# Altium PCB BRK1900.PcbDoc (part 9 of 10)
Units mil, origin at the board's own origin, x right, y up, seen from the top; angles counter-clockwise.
Board outline 8858.27 x 5905.51 mil, 10 copper layers (L1-TOP, L2-GND, L3-SIG1, L4-GND, L5-PWR, L6-PWR, L7-GND, L8-SIG2, L9-GND, L10-BOT), stack 48.824 mil thick; 507 components, 607 nets, 2498 pads, 2210 vias.
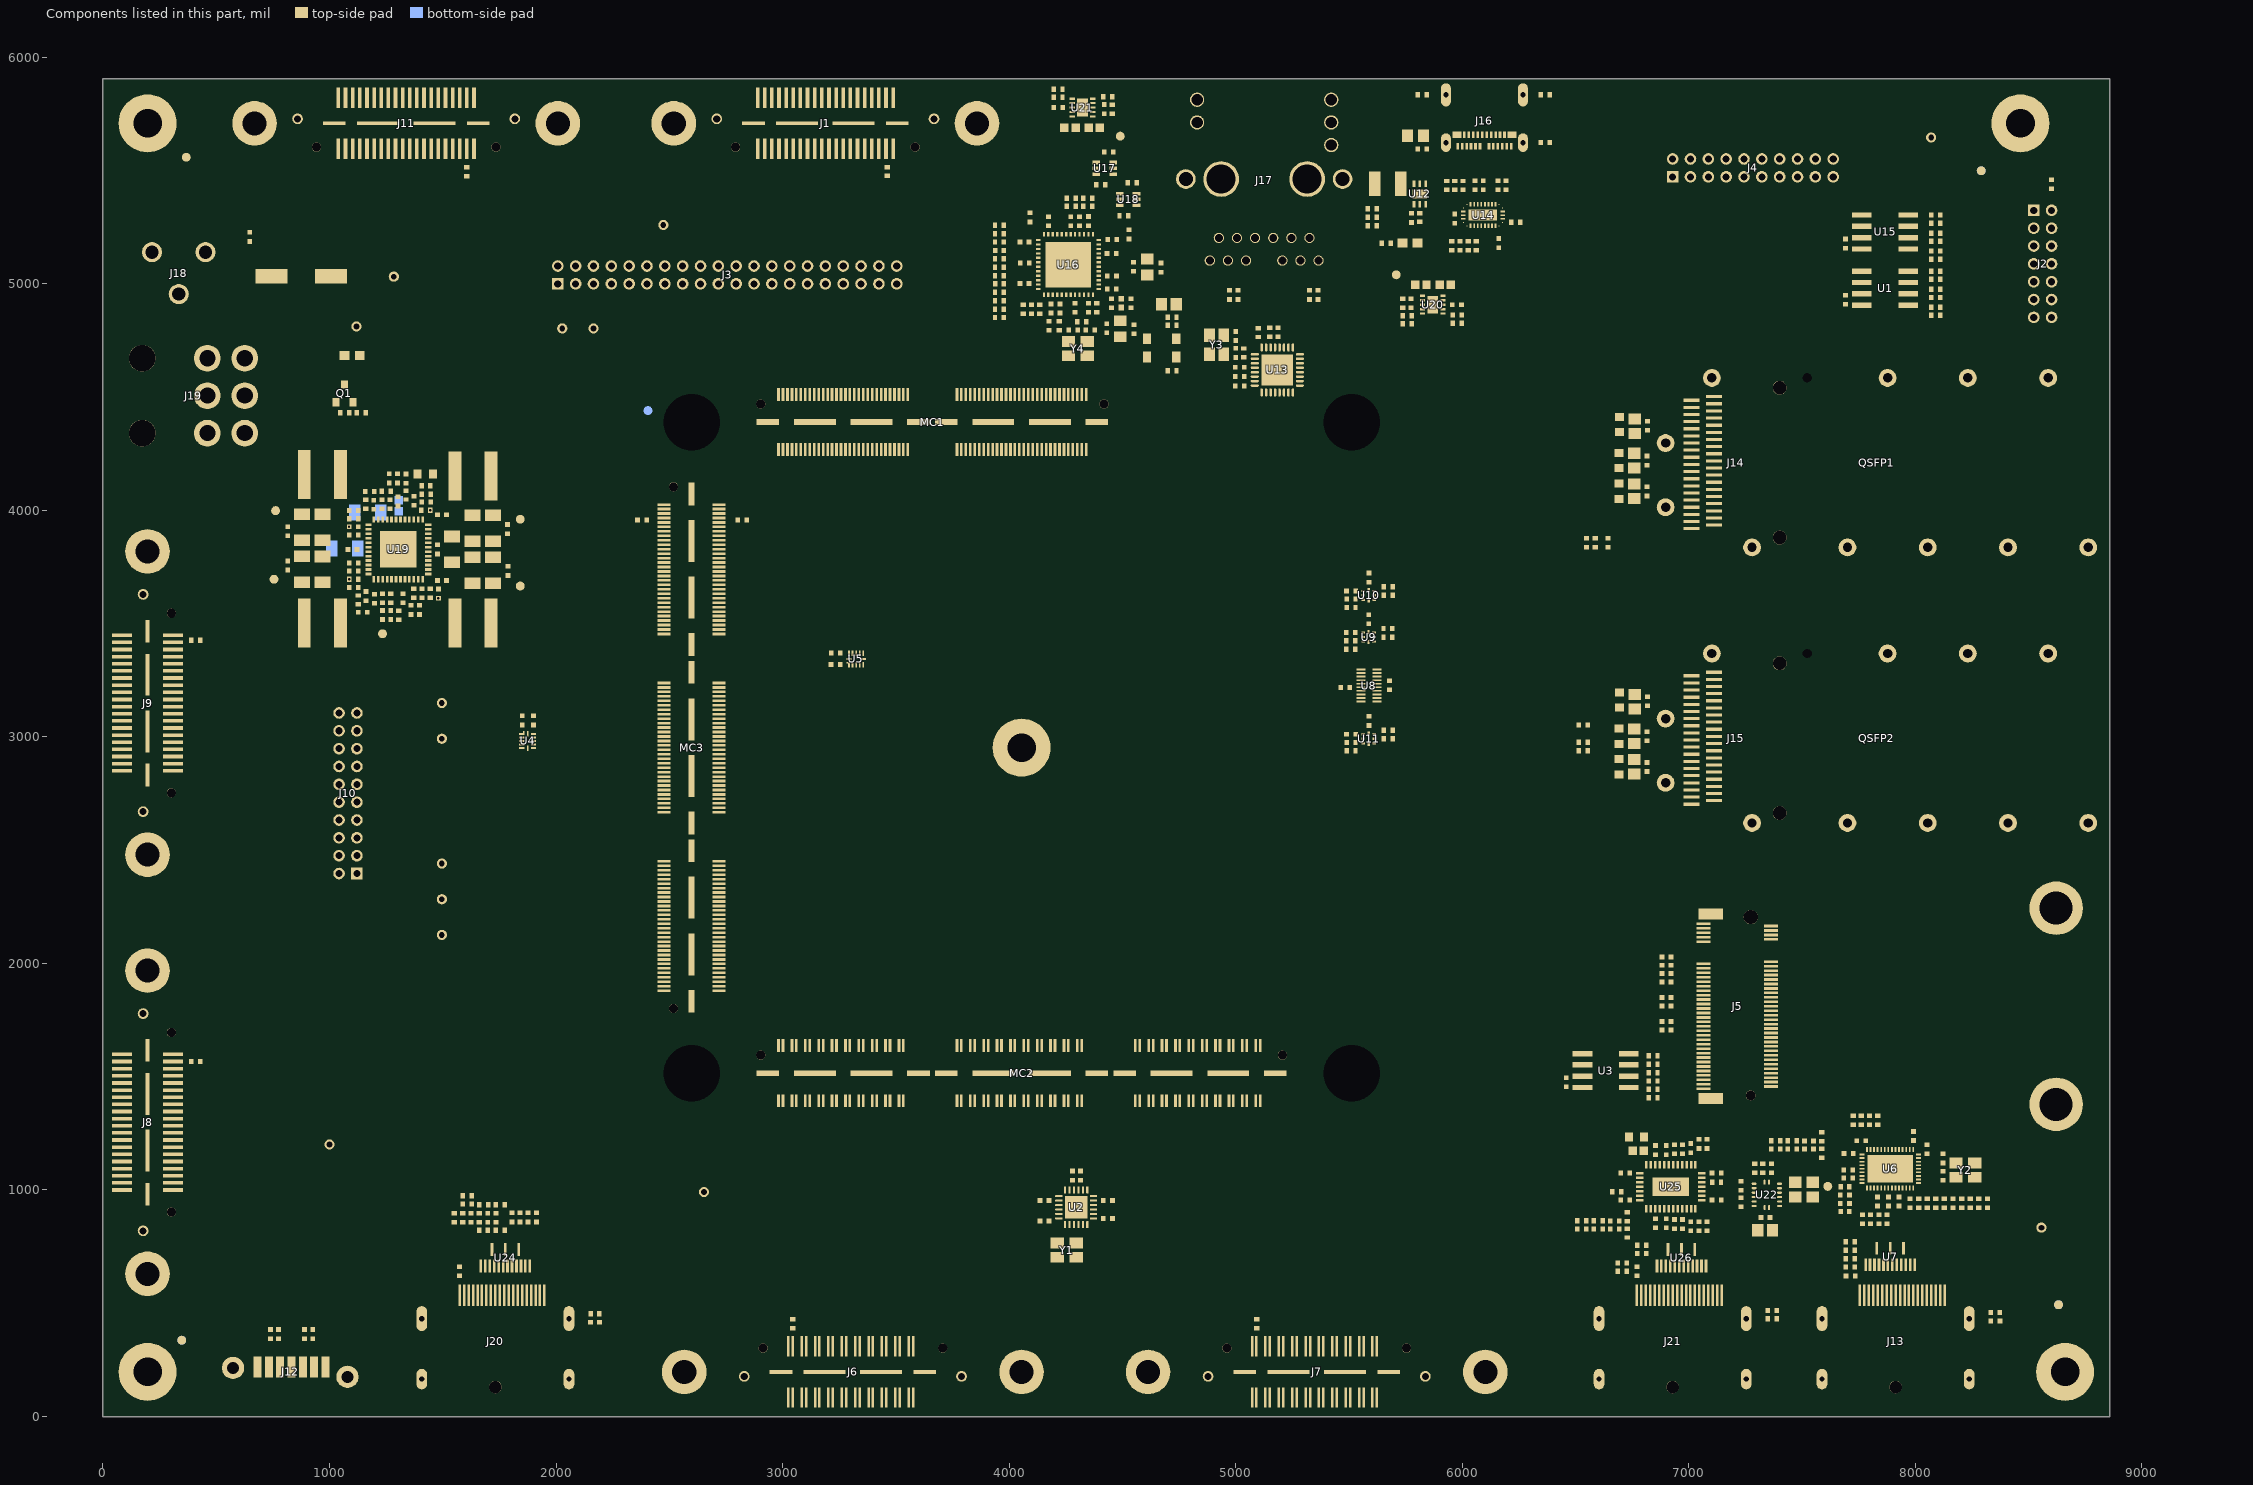
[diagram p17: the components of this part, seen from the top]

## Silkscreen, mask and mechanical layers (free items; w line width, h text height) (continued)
Fab Notes:
  drawing of 90 lines, arcs and shapes, not listed
  text "LAYER STACKUP TABLE" at 6751.97,9126.93 h50
  text "S" at 11192.76,9012.43 h90.87
  text "i" at 11229.19,9012.43 h90.87
  text "n" at 11250,9012.43 h90.87
  text "g" at 11291.64,9012.43 h90.87
  text "l" at 11328.07,9012.43 h90.87
  text "e" at 11348.89,9012.43 h90.87
  text "-" at 11390.52,9012.42 h90.87
  text "E" at 11416.54,9012.43 h90.87
  text "n" at 11452.97,9012.43 h90.87
  text "d" at 11494.61,9012.43 h90.87
  text "e" at 11536.24,9012.43 h90.87
  text "d" at 11577.88,9012.43 h90.87
  text "D" at 12207.26,9012.43 h90.87
  text "i" at 12254.1,9012.43 h90.87
  text "f" at 12274.91,9012.43 h90.87
  text "f" at 12300.94,9012.43 h90.87
  text "e" at 12326.96,9012.43 h90.87
  text "r" at 12368.59,9012.43 h90.87
  text "e" at 12394.61,9012.43 h90.87
  text "n" at 12436.25,9012.43 h90.87
  text "t" at 12477.88,9012.43 h90.87
  text "i" at 12503.91,9012.43 h90.87
  text "a" at 12524.72,9012.43 h90.87
  text "l" at 12561.15,9012.43 h90.87
  text "D" at 12639.07,9012.43 h90.87
  text "i" at 12685.91,9012.43 h90.87
  text "f" at 12706.73,9012.43 h90.87
  text "f" at 12732.75,9012.43 h90.87
  text "e" at 12758.77,9012.43 h90.87
  text "r" at 12800.41,9012.43 h90.87
  text "e" at 12826.43,9012.43 h90.87
  text "n" at 12868.06,9012.43 h90.87
  text "t" at 12909.7,9012.43 h90.87
  text "i" at 12935.72,9012.43 h90.87
  text "a" at 12956.54,9012.43 h90.87
  text "l" at 12992.97,9012.43 h90.87
  text "D" at 13122.91,9012.43 h90.87
  text "i" at 13169.75,9012.43 h90.87
  text "f" at 13190.57,9012.43 h90.87
  text "f" at 13216.59,9012.43 h90.87
  text "e" at 13242.61,9012.43 h90.87
  text "r" at 13284.25,9012.43 h90.87
  text "e" at 13310.27,9012.43 h90.87
  text "n" at 13351.9,9012.43 h90.87
  text "t" at 13393.54,9012.43 h90.87
  text "i" at 13419.56,9012.43 h90.87
  text "a" at 13440.38,9012.43 h90.87
  text "l" at 13476.81,9012.43 h90.87
  text "D" at 13554.72,9012.43 h90.87
  text "i" at 13601.56,9012.43 h90.87
  text "f" at 13622.38,9012.43 h90.87
  text "f" at 13648.4,9012.43 h90.87
  text "e" at 13674.42,9012.43 h90.87
  text "r" at 13716.06,9012.43 h90.87
  text "e" at 13742.08,9012.43 h90.87
  text "n" at 13783.72,9012.43 h90.87
  text "t" at 13825.35,9012.43 h90.87
  text "i" at 13851.37,9012.43 h90.87
  text "a" at 13872.19,9012.43 h90.87
  text "l" at 13908.62,9012.43 h90.87
  text "M" at 9938.93,9005.69 h85.82
  text "a" at 9996.18,9005.69 h85.82
  text "t" at 10037.82,9005.69 h85.82
  text "e" at 10058.64,9005.69 h85.82
  text "r" at 10100.27,9005.69 h85.82
  text "i" at 10126.29,9005.69 h85.82
  text "a" at 10141.91,9005.69 h85.82
  text "l" at 10183.54,9005.69 h85.82
  text "C" at 10339.53,8908.34 h90.87
  text "o" at 10381.17,8908.34 h90.87
  text "p" at 10422.8,8908.34 h90.87
  text "p" at 10464.44,8908.34 h90.87
  text "e" at 10506.07,8908.34 h90.87
  text "r" at 10547.71,8908.34 h90.87
  text "T" at 11322.82,8908.34 h90.87
  text "r" at 11359.25,8908.34 h90.87
  text "a" at 11385.27,8908.34 h90.87
  text "c" at 11421.7,8908.34 h90.87
  text "e" at 11452.93,8908.34 h90.87
  text "S" at 11681.8,8908.34 h90.87
  text "i" at 11718.23,8908.34 h90.87
  text "n" at 11739.05,8908.34 h90.87
  text "g" at 11780.68,8908.34 h90.87
  text "l" at 11817.11,8908.34 h90.87
  text "e" at 11837.93,8908.34 h90.87
  text "-" at 11879.56,8908.33 h90.87
  text "E" at 11905.59,8908.34 h90.87
  text "n" at 11942.02,8908.34 h90.87
  text "d" at 11983.65,8908.34 h90.87
  text "e" at 12025.29,8908.34 h90.87
  text "d" at 12066.92,8908.34 h90.87
  text "T" at 12311.31,8908.34 h90.87
  text "r" at 12347.74,8908.34 h90.87
  text "a" at 12373.76,8908.34 h90.87
  text "c" at 12410.19,8908.34 h90.87
  text "e" at 12441.42,8908.34 h90.87
  text "T" at 12743.12,8908.34 h90.87
  text "r" at 12779.55,8908.34 h90.87
  text "a" at 12805.57,8908.34 h90.87
  text "c" at 12842.01,8908.34 h90.87
  text "e" at 12873.23,8908.34 h90.87
  text "T" at 13226.96,8908.34 h90.87
  text "r" at 13263.39,8908.34 h90.87
  text "a" at 13289.41,8908.34 h90.87
  text "c" at 13325.84,8908.34 h90.87
  text "e" at 13357.07,8908.34 h90.87
  text "T" at 13658.78,8908.34 h90.87
  text "r" at 13695.21,8908.34 h90.87
  text "a" at 13721.23,8908.34 h90.87
  text "c" at 13757.66,8908.34 h90.87
  text "e" at 13788.88,8908.34 h90.87
  text "P" at 9923.33,8906.8 h85.82
  text "r" at 9975.37,8906.8 h85.82
  text "e" at 10001.39,8906.8 h85.82
  text "s" at 10043.03,8906.8 h85.82
  text "s" at 10084.66,8906.8 h85.82
  text "e" at 10126.3,8906.8 h85.82
  text "d" at 10167.93,8906.8 h85.82
  text "G" at 7769.46,8807.92 h85.82
  text "e" at 7826.71,8807.92 h85.82
  text "r" at 7868.35,8807.92 h85.82
  text "b" at 7894.37,8807.92 h85.82
  text "e" at 7936,8807.92 h85.82
  text "r" at 7977.64,8807.92 h85.82
  text "M" at 9470.7,8807.92 h85.82
  text "a" at 9527.95,8807.92 h85.82
  text "t" at 9569.59,8807.92 h85.82
  text "e" at 9590.4,8807.92 h85.82
  text "r" at 9632.04,8807.92 h85.82
  text "i" at 9658.06,8807.92 h85.82
  text "a" at 9673.67,8807.92 h85.82
  text "l" at 9715.31,8807.92 h85.82
  text "E" at 9751.74,8807.92 h85.82
  text "r" at 9803.78,8807.92 h85.82
  text "T" at 9892.11,8807.92 h85.82
  text "h" at 9938.95,8807.92 h85.82
  text "i" at 9980.59,8807.92 h85.82
  text "c" at 9996.2,8807.92 h85.82
  text "k" at 10037.83,8807.92 h85.82
  text "n" at 10074.27,8807.92 h85.82
  text "e" at 10115.9,8807.92 h85.82
  text "s" at 10157.54,8807.92 h85.82
  text "s" at 10199.17,8807.92 h85.82
  text "T" at 10297.91,8804.25 h90.87
  text "h" at 10334.34,8804.25 h90.87
  text "i" at 10375.98,8804.25 h90.87
  text "c" at 10396.8,8804.25 h90.87
  text "k" at 10428.02,8804.25 h90.87
  text "n" at 10464.45,8804.25 h90.87
  text "e" at 10506.09,8804.25 h90.87
  text "s" at 10547.72,8804.25 h90.87
  text "s" at 10578.95,8804.25 h90.87
  text "C" at 10755.74,8804.25 h90.87
  text "o" at 10797.37,8804.25 h90.87
  text "p" at 10839.01,8804.26 h90.87
  text "p" at 10880.64,8804.26 h90.87
  text "e" at 10922.28,8804.25 h90.87
  text "r" at 10963.91,8804.25 h90.87
  text "I" at 11229.17,8804.25 h90.87
  text "m" at 11249.99,8804.25 h90.87
  text "p" at 11312.44,8804.26 h90.87
  text "e" at 11354.08,8804.25 h90.87
  text "d" at 11395.71,8804.25 h90.87
  text "a" at 11437.35,8804.25 h90.87
  text "n" at 11473.78,8804.25 h90.87
  text "c" at 11515.41,8804.25 h90.87
  text "e" at 11546.64,8804.25 h90.87
  text "T" at 11702.61,8804.25 h90.87
  text "r" at 11739.04,8804.25 h90.87
  text "a" at 11765.06,8804.25 h90.87
  text "c" at 11801.49,8804.25 h90.87
  text "e" at 11832.72,8804.25 h90.87
  text "W" at 11889.97,8804.25 h90.87
  text "i" at 11957.62,8804.25 h90.87
  text "d" at 11978.44,8804.25 h90.87
  text "t" at 12020.07,8804.25 h90.87
  text "h" at 12046.1,8804.25 h90.87
  text "I" at 12217.66,8804.25 h90.87
  text "m" at 12238.48,8804.25 h90.87
  text "p" at 12300.93,8804.26 h90.87
  text "e" at 12342.57,8804.25 h90.87
  text "d" at 12384.2,8804.25 h90.87
  text "a" at 12425.84,8804.25 h90.87
  text "n" at 12462.27,8804.25 h90.87
  text "c" at 12503.9,8804.25 h90.87
  text "e" at 12535.13,8804.25 h90.87
  text "W" at 12618.26,8804.25 h90.87
  text "i" at 12685.92,8804.25 h90.87
  text "d" at 12706.73,8804.25 h90.87
  text "t" at 12748.37,8804.25 h90.87
  text "h" at 12774.39,8804.25 h90.87
  text "/" at 12816.03,8804.26 h90.87
  text "S" at 12847.25,8804.25 h90.87
  text "p" at 12883.68,8804.26 h90.87
  text "a" at 12925.32,8804.25 h90.87
  text "c" at 12961.75,8804.25 h90.87
  text "e" at 12992.98,8804.25 h90.87
  text "I" at 13133.32,8804.25 h90.87
  text "m" at 13154.13,8804.25 h90.87
  text "p" at 13216.59,8804.26 h90.87
  text "e" at 13258.22,8804.25 h90.87
  text "d" at 13299.86,8804.25 h90.87
  text "a" at 13341.49,8804.25 h90.87
  text "n" at 13377.92,8804.25 h90.87
  text "c" at 13419.56,8804.25 h90.87
  text "e" at 13450.78,8804.25 h90.87
  text "W" at 13533.91,8804.25 h90.87
  text "i" at 13601.57,8804.25 h90.87
  text "d" at 13622.39,8804.25 h90.87
  text "t" at 13664.02,8804.25 h90.87
  text "h" at 13690.04,8804.25 h90.87
  text "/" at 13731.68,8804.26 h90.87
  text "S" at 13762.91,8804.25 h90.87
  text "p" at 13799.34,8804.26 h90.87
  text "a" at 13840.97,8804.25 h90.87
  text "c" at 13877.4,8804.25 h90.87
  text "e" at 13908.63,8804.25 h90.87
  text "L" at 6770.57,8709.04 h85.82
  text "a" at 6812.2,8709.04 h85.82
  text "y" at 6853.84,8709.02 h85.82
  text "e" at 6890.27,8709.04 h85.82
  text "r" at 6931.9,8709.04 h85.82
  text "L" at 7030.7,8709.04 h85.82
  text "a" at 7072.33,8709.04 h85.82
  text "y" at 7113.97,8709.02 h85.82
  text "e" at 7150.4,8709.04 h85.82
  text "r" at 7192.03,8709.04 h85.82
  text "N" at 7238.87,8709.04 h85.82
  text "a" at 7290.92,8709.04 h85.82
  text "m" at 7332.55,8709.04 h85.82
  text "e" at 7400.21,8709.04 h85.82
  text "L" at 7769.46,8709.04 h85.82
  text "a" at 7811.1,8709.04 h85.82
  text "y" at 7852.73,8709.02 h85.82
  text "e" at 7889.16,8709.04 h85.82
  text "r" at 7930.8,8709.04 h85.82
  text "M" at 8081.62,8709.04 h85.82
  text "a" at 8138.86,8709.04 h85.82
  text "t" at 8180.5,8709.04 h85.82
  text "e" at 8201.32,8709.04 h85.82
  text "r" at 8242.95,8709.04 h85.82
  text "i" at 8268.97,8709.04 h85.82
  text "a" at 8284.59,8709.04 h85.82
  text "l" at 8326.22,8709.04 h85.82
  text "T" at 8362.65,8709.04 h85.82
  text "y" at 8409.49,8709.02 h85.82
  text "p" at 8445.92,8709.02 h85.82
  text "e" at 8487.56,8709.04 h85.82
  text "M" at 8617.48,8709.04 h85.82
  text "a" at 8674.73,8709.04 h85.82
  text "t" at 8716.36,8709.04 h85.82
  text "e" at 8737.18,8709.04 h85.82
  text "r" at 8778.82,8709.04 h85.82
  text "i" at 8804.84,8709.04 h85.82
  text "a" at 8820.45,8709.04 h85.82
  text "l" at 8862.09,8709.04 h85.82
  text "C" at 8898.52,8709.04 h85.82
  text "o" at 8955.77,8709.04 h85.82
  text "n" at 8997.4,8709.04 h85.82
  text "s" at 9039.04,8709.04 h85.82
  text "t" at 9080.67,8709.04 h85.82
  text "r" at 9101.49,8709.04 h85.82
  text "u" at 9127.51,8709.04 h85.82
  text "c" at 9169.15,8709.04 h85.82
  text "t" at 9210.78,8709.04 h85.82
  text "i" at 9231.6,8709.04 h85.82
  text "o" at 9247.21,8709.04 h85.82
  text "n" at 9288.85,8709.04 h85.82
  text "(" at 9517.53,8709.02 h85.82
  text "1" at 9543.55,8709.04 h85.82
  text "G" at 9606,8709.04 h85.82
  text "H" at 9663.25,8709.04 h85.82
  text "z" at 9715.29,8709.04 h85.82
  text ")" at 9756.93,8709.02 h85.82
  text "(" at 9990.96,8709.02 h85.82
  text "m" at 10016.98,8709.04 h85.82
  text "i" at 10084.64,8709.04 h85.82
  text "l" at 10100.25,8709.04 h85.82
  text ")" at 10115.87,8709.02 h85.82
  text "(" at 10375.95,8700.17 h90.87
  text "u" at 10401.97,8700.16 h90.87
  text "m" at 10443.61,8700.16 h90.87
  text ")" at 10506.06,8700.17 h90.87
  text "W" at 10682.9,8700.16 h90.87
  text "e" at 10750.56,8700.16 h90.87
  text "i" at 10792.19,8700.16 h90.87
  text "g" at 10813.01,8700.17 h90.87
  text "h" at 10849.44,8700.16 h90.87
  text "t" at 10891.08,8700.16 h90.87
  text "(" at 10932.71,8700.17 h90.87
  text "o" at 10958.74,8700.16 h90.87
  text "z" at 11000.37,8700.16 h90.87
  text ")" at 11031.6,8700.17 h90.87
  text "(" at 11291.6,8700.17 h90.87
  text "o" at 11317.63,8700.16 h90.87
  text "h" at 11359.26,8700.16 h90.87
  text "m" at 11400.9,8700.16 h90.87
  text "s" at 11463.35,8700.16 h90.87
  text ")" at 11494.58,8700.17 h90.87
  text "(" at 11801.46,8700.17 h90.87
  text "m" at 11827.48,8700.16 h90.87
  text "i" at 11889.93,8700.16 h90.87
  text "l" at 11910.75,8700.16 h90.87
  text "s" at 11931.57,8700.16 h90.87
  text ")" at 11962.79,8700.17 h90.87
  text "(" at 12280.09,8700.17 h90.87
  text "o" at 12306.12,8700.16 h90.87
  text "h" at 12347.75,8700.16 h90.87
  text "m" at 12389.39,8700.16 h90.87
  text "s" at 12451.84,8700.16 h90.87
  text ")" at 12483.06,8700.17 h90.87
  text "(" at 12732.72,8700.17 h90.87
  text "m" at 12758.74,8700.16 h90.87
  text "i" at 12821.19,8700.16 h90.87
  text "l" at 12842.01,8700.16 h90.87
  text "s" at 12862.83,8700.16 h90.87
  text ")" at 12894.05,8700.17 h90.87
  text "(" at 13195.75,8700.17 h90.87
  text "o" at 13221.77,8700.16 h90.87
  text "h" at 13263.4,8700.16 h90.87
  text "m" at 13305.04,8700.16 h90.87
  text "s" at 13367.49,8700.16 h90.87
  text ")" at 13398.72,8700.17 h90.87
  text "(" at 13648.37,8700.17 h90.87
  text "m" at 13674.39,8700.16 h90.87
  text "i" at 13736.84,8700.16 h90.87
  text "l" at 13757.66,8700.16 h90.87
  text "s" at 13778.48,8700.16 h90.87
  text ")" at 13809.71,8700.17 h90.87
  text "O" at 7030.7,8552.9 h85.82
  text "v" at 7093.15,8552.91 h85.82
  text "e" at 7129.58,8552.9 h85.82
  text "r" at 7171.21,8552.91 h85.82
  text "l" at 7197.24,8552.91 h85.82
  text "a" at 7212.85,8552.9 h85.82
  text "y" at 7254.48,8552.89 h85.82
  text "T" at 7311.73,8552.91 h85.82
  text "o" at 7358.57,8552.9 h85.82
  text "p" at 7400.21,8552.89 h85.82
  text "G" at 7769.46,8552.9 h85.82
  text "T" at 7826.71,8552.91 h85.82
  text "O" at 7873.55,8552.9 h85.82
  text "S" at 8081.62,8552.9 h85.82
  text "i" at 8133.66,8552.91 h85.82
  text "l" at 8149.27,8552.91 h85.82
  text "k" at 8164.89,8552.91 h85.82
  text "s" at 8201.32,8552.9 h85.82
  text "c" at 8242.95,8552.9 h85.82
  text "r" at 8284.59,8552.91 h85.82
  text "e" at 8310.61,8552.9 h85.82
  text "e" at 8352.24,8552.9 h85.82
  text "n" at 8393.88,8552.91 h85.82
  text "S" at 7030.7,8448.82 h85.82
  text "o" at 7082.74,8448.82 h85.82
  text "l" at 7124.38,8448.82 h85.82
  text "d" at 7139.99,8448.82 h85.82
  text "e" at 7181.62,8448.82 h85.82
  text "r" at 7223.26,8448.82 h85.82
  text "M" at 7270.1,8448.82 h85.82
  text "a" at 7327.35,8448.82 h85.82
  text "s" at 7368.98,8448.82 h85.82
  text "k" at 7410.62,8448.82 h85.82
  text "T" at 7467.86,8448.82 h85.82
  text "o" at 7514.7,8448.82 h85.82
  text "p" at 7556.34,8448.8 h85.82
  text "G" at 7769.46,8448.82 h85.82
  text "T" at 7826.71,8448.82 h85.82
  text "S" at 7873.55,8448.82 h85.82
  text "S" at 8081.62,8448.82 h85.82
  text "o" at 8133.66,8448.82 h85.82
  text "l" at 8175.3,8448.82 h85.82
  text "d" at 8190.91,8448.82 h85.82
  text "e" at 8232.54,8448.82 h85.82
  text "r" at 8274.18,8448.82 h85.82
  text "R" at 8321.02,8448.82 h85.82
  text "e" at 8378.27,8448.82 h85.82
  text "s" at 8419.9,8448.82 h85.82
  text "i" at 8461.54,8448.82 h85.82
  text "s" at 8477.15,8448.82 h85.82
  text "t" at 8518.78,8448.82 h85.82
  text "3" at 9605.97,8445.15 h90.87
  text "." at 9642.4,8445.15 h90.87
  text "5" at 9663.22,8445.15 h90.87
  text "1" at 6770.57,8344.73 h85.82
  text "L" at 7030.7,8344.73 h85.82
  text "1" at 7072.33,8344.73 h85.82
  text "-" at 7113.97,8344.74 h85.82
  text "T" at 7139.99,8344.73 h85.82
  text "O" at 7186.83,8344.73 h85.82
  text "P" at 7249.28,8344.73 h85.82
  text "G" at 7769.46,8344.73 h85.82
  text "T" at 7826.71,8344.73 h85.82
  text "L" at 7873.55,8344.73 h85.82
  text "C" at 8081.62,8344.73 h85.82
  text "o" at 8138.86,8344.73 h85.82
  text "p" at 8180.5,8344.72 h85.82
  text "p" at 8222.13,8344.72 h85.82
  text "e" at 8263.77,8344.73 h85.82
  text "r" at 8305.4,8344.73 h85.82
  text "3" at 10370.75,8341.06 h90.87
  text "0" at 10407.18,8341.06 h90.87
  text "-" at 10443.61,8341.05 h90.87
  text "5" at 10469.63,8341.06 h90.87
  text "0" at 10506.06,8341.06 h90.87
  text "1" at 10672.5,8341.06 h90.87
  text "/" at 10708.93,8341.07 h90.87
  text "3" at 10740.15,8341.06 h90.87
  text "+" at 10792.2,8341.06 h90.87
  text "p" at 10844.24,8341.07 h90.87
  text "l" at 10885.88,8341.06 h90.87
  text "a" at 10906.69,8341.06 h90.87
  text "t" at 10943.13,8341.06 h90.87
  text "i" at 10969.15,8341.06 h90.87
  text "n" at 10989.97,8341.06 h90.87
  text "g" at 11031.6,8341.07 h90.87
  text "5" at 11374.85,8341.06 h90.87
  text "0" at 11411.28,8341.06 h90.87
  text "4" at 11832.67,8341.06 h90.87
  text "." at 11869.1,8341.06 h90.87
  text "5" at 11889.92,8341.06 h90.87
  text "5" at 11926.35,8341.06 h90.87
  text "9" at 12358.13,8341.06 h90.87
  text "0" at 12394.56,8341.06 h90.87
  text "4" at 12665.08,8341.06 h90.87
  text "." at 12701.51,8341.06 h90.87
  text "0" at 12722.33,8341.06 h90.87
  text "5" at 12758.76,8341.06 h90.87
  text "/" at 12810.81,8341.07 h90.87
  text "4" at 12857.65,8341.06 h90.87
  text "." at 12894.08,8341.06 h90.87
  text "9" at 12914.89,8341.06 h90.87
  text "5" at 12951.32,8341.06 h90.87
  text "1" at 13258.18,8341.06 h90.87
  text "0" at 13294.61,8341.06 h90.87
  text "0" at 13331.04,8341.06 h90.87
  text "3" at 13580.74,8341.06 h90.87
  text "." at 13617.17,8341.06 h90.87
  text "3" at 13637.98,8341.06 h90.87
  text "0" at 13674.42,8341.06 h90.87
  text "/" at 13726.46,8341.07 h90.87
  text "5" at 13773.3,8341.06 h90.87
  text "." at 13809.73,8341.06 h90.87
  text "7" at 13830.55,8341.06 h90.87
  text "0" at 13866.98,8341.06 h90.87
  text "P" at 8081.62,8240.64 h85.82
  text "r" at 8133.66,8240.64 h85.82
  text "e" at 8159.68,8240.64 h85.82
  text "p" at 8201.32,8240.63 h85.82
  text "r" at 8242.95,8240.64 h85.82
  text "e" at 8268.97,8240.64 h85.82
  text "g" at 8310.61,8240.63 h85.82
  text "P" at 8617.48,8236.97 h90.87
  text "P" at 8659.12,8236.97 h90.87
  text "(" at 8700.75,8236.98 h90.87
  text "1" at 8726.77,8236.97 h90.87
  text "0" at 8763.2,8236.97 h90.87
  text "8" at 8799.63,8236.97 h90.87
  text "0" at 8836.07,8236.97 h90.87
  text ")" at 8872.5,8236.98 h90.87
  text "R" at 8898.52,8236.97 h90.87
  text "C" at 8940.15,8236.97 h90.87
  text "7" at 8981.79,8236.97 h90.87
  text "1" at 9018.22,8236.97 h90.87
  text "3" at 9605.97,8236.97 h90.87
  text "." at 9642.4,8236.97 h90.87
  text "9" at 9663.22,8236.97 h90.87
  text "2" at 9985.76,8236.97 h90.87
  text "." at 10022.19,8236.97 h90.87
  text "9" at 10043.01,8236.97 h90.87
  text "7" at 10079.44,8236.97 h90.87
  text "2" at 10115.87,8236.97 h90.87
  text "2" at 6770.57,8136.55 h85.82
  text "L" at 7030.7,8136.55 h85.82
  text "2" at 7072.33,8136.55 h85.82
  text "-" at 7113.97,8136.57 h85.82
  text "G" at 7139.99,8136.55 h85.82
  text "N" at 7197.24,8136.55 h85.82
  text "D" at 7249.28,8136.55 h85.82
  text "G" at 7769.46,8136.55 h85.82
  text "1" at 7826.71,8136.55 h85.82
  text "C" at 8081.62,8136.55 h85.82
  text "o" at 8138.86,8136.55 h85.82
  text "p" at 8180.5,8136.54 h85.82
  text "p" at 8222.13,8136.54 h85.82
  text "e" at 8263.77,8136.55 h85.82
  text "r" at 8305.4,8136.55 h85.82
  text "1" at 10417.57,8132.89 h90.87
  text "5" at 10454,8132.89 h90.87
  text "1" at 10818.17,8132.89 h90.87
  text "/" at 10854.6,8132.89 h90.87
  text "2" at 10885.83,8132.89 h90.87
  text "C" at 8081.62,8032.47 h85.82
  text "o" at 8138.86,8032.47 h85.82
  text "r" at 8180.5,8032.47 h85.82
  text "e" at 8206.52,8032.47 h85.82
  text "2" at 8617.48,8028.8 h90.87
  text "*" at 8653.91,8028.79 h90.87
  text "7" at 8690.34,8028.8 h90.87
  text "6" at 8726.77,8028.8 h90.87
  text "2" at 8763.2,8028.8 h90.87
  text "8" at 8799.63,8028.8 h90.87
  text "(" at 8851.68,8028.8 h90.87
  text "R" at 8877.7,8028.8 h90.87
  text "C" at 8919.34,8028.8 h90.87
  text "5" at 8960.97,8028.8 h90.87
  text "0" at 8997.4,8028.8 h90.87
  text ")" at 9033.83,8028.8 h90.87
  text "4" at 9605.97,8028.8 h90.87
  text "." at 9642.4,8028.8 h90.87
  text "6" at 9663.22,8028.8 h90.87
  text "1" at 9964.95,8028.8 h90.87
  text "6" at 10001.38,8028.8 h90.87
  text "." at 10037.81,8028.8 h90.87
  text "0" at 10058.63,8028.8 h90.87
  text "0" at 10095.06,8028.8 h90.87
  text "0" at 10131.49,8028.8 h90.87
  text "3" at 6770.57,7928.38 h85.82
  text "L" at 7030.7,7928.38 h85.82
  text "3" at 7072.33,7928.38 h85.82
  text "-" at 7113.97,7928.39 h85.82
  text "S" at 7139.99,7928.38 h85.82
  text "I" at 7192.03,7928.38 h85.82
  text "G" at 7207.65,7928.38 h85.82
  text "1" at 7264.89,7928.38 h85.82
  text "G" at 7769.46,7928.38 h85.82
  text "2" at 7826.71,7928.38 h85.82
  text "C" at 8081.62,7928.38 h85.82
  text "o" at 8138.86,7928.38 h85.82
  text "p" at 8180.5,7928.37 h85.82
  text "p" at 8222.13,7928.37 h85.82
  text "e" at 8263.77,7928.38 h85.82
  text "r" at 8305.4,7928.38 h85.82
  text "1" at 10417.57,7924.71 h90.87
  text "5" at 10454,7924.71 h90.87
  text "1" at 10818.17,7924.71 h90.87
  text "/" at 10854.6,7924.72 h90.87
  text "2" at 10885.83,7924.71 h90.87
  text "5" at 11374.85,7924.71 h90.87
  text "0" at 11411.28,7924.71 h90.87
  text "4" at 11832.67,7924.71 h90.87
  text "." at 11869.1,7924.71 h90.87
  text "0" at 11889.92,7924.71 h90.87
  text "5" at 11926.35,7924.71 h90.87
  text "9" at 12358.13,7924.71 h90.87
  text "0" at 12394.56,7924.71 h90.87
  text "3" at 12665.08,7924.71 h90.87
  text "." at 12701.51,7924.71 h90.87
  text "8" at 12722.33,7924.71 h90.87
  text "5" at 12758.76,7924.71 h90.87
  text "/" at 12810.81,7924.72 h90.87
  text "5" at 12857.65,7924.71 h90.87
  text "." at 12894.08,7924.71 h90.87
  text "1" at 12914.89,7924.71 h90.87
  text "5" at 12951.32,7924.71 h90.87
  text "1" at 13258.18,7924.71 h90.87
  text "0" at 13294.61,7924.71 h90.87
  text "0" at 13331.04,7924.71 h90.87
  text "3" at 13580.74,7924.71 h90.87
  text "." at 13617.17,7924.71 h90.87
  text "1" at 13637.98,7924.71 h90.87
  text "5" at 13674.42,7924.71 h90.87
  text "/" at 13726.46,7924.72 h90.87
  text "5" at 13773.3,7924.71 h90.87
  text "." at 13809.73,7924.71 h90.87
  text "8" at 13830.55,7924.71 h90.87
  text "5" at 13866.98,7924.71 h90.87
  text "P" at 8081.62,7824.29 h85.82
  text "r" at 8133.66,7824.29 h85.82
  text "e" at 8159.68,7824.29 h85.82
  text "p" at 8201.32,7824.28 h85.82
  text "r" at 8242.95,7824.29 h85.82
  text "e" at 8268.97,7824.29 h85.82
  text "g" at 8310.61,7824.28 h85.82
  text "P" at 8617.48,7820.62 h90.87
  text "P" at 8659.12,7820.62 h90.87
  text "(" at 8700.75,7820.63 h90.87
  text "1" at 8726.77,7820.62 h90.87
  text "0" at 8763.2,7820.62 h90.87
  text "8" at 8799.63,7820.62 h90.87
  text "0" at 8836.07,7820.62 h90.87
  text ")" at 8872.5,7820.63 h90.87
  text "R" at 8898.52,7820.62 h90.87
  text "C" at 8940.15,7820.62 h90.87
  text "7" at 8981.79,7820.62 h90.87
  text "1" at 9018.22,7820.62 h90.87
  text "3" at 9605.97,7820.62 h90.87
  text "." at 9642.4,7820.62 h90.87
  text "9" at 9663.22,7820.62 h90.87
  text "3" at 9985.76,7820.62 h90.87
  text "." at 10022.19,7820.62 h90.87
  text "0" at 10043.01,7820.62 h90.87
  text "5" at 10079.44,7820.62 h90.87
  text "5" at 10115.87,7820.62 h90.87
  text "4" at 6770.57,7720.2 h85.82
  text "L" at 7030.7,7720.2 h85.82
  text "4" at 7072.33,7720.2 h85.82
  text "-" at 7113.97,7720.22 h85.82
  text "G" at 7139.99,7720.2 h85.82
  text "N" at 7197.24,7720.2 h85.82
  text "D" at 7249.28,7720.2 h85.82
  text "G" at 7769.46,7720.2 h85.82
  text "3" at 7826.71,7720.2 h85.82
  text "C" at 8081.62,7720.2 h85.82
  text "o" at 8138.86,7720.2 h85.82
  text "p" at 8180.5,7720.19 h85.82
  text "p" at 8222.13,7720.19 h85.82
  text "e" at 8263.77,7720.2 h85.82
  text "r" at 8305.4,7720.2 h85.82
  text "1" at 10417.57,7716.54 h90.87
  text "5" at 10454,7716.54 h90.87
  text "1" at 10818.17,7716.54 h90.87
  text "/" at 10854.6,7716.54 h90.87
  text "2" at 10885.83,7716.54 h90.87
  text "C" at 8081.62,7616.12 h85.82
  text "o" at 8138.86,7616.12 h85.82
  text "r" at 8180.5,7616.12 h85.82
  text "e" at 8206.52,7616.12 h85.82
  text "2" at 8617.48,7612.45 h90.87
  text "*" at 8653.91,7612.44 h90.87
  text "7" at 8690.34,7612.45 h90.87
  text "6" at 8726.77,7612.45 h90.87
  text "2" at 8763.2,7612.45 h90.87
  text "8" at 8799.63,7612.45 h90.87
  text "(" at 8851.68,7612.45 h90.87
  text "R" at 8877.7,7612.45 h90.87
  text "C" at 8919.34,7612.45 h90.87
  text "5" at 8960.97,7612.45 h90.87
  text "0" at 8997.4,7612.45 h90.87
  text ")" at 9033.83,7612.45 h90.87
  text "4" at 9605.97,7612.45 h90.87
  text "." at 9642.4,7612.45 h90.87
  text "6" at 9663.22,7612.45 h90.87
  text "1" at 9964.95,7612.45 h90.87
  text "6" at 10001.38,7612.45 h90.87
  text "." at 10037.81,7612.45 h90.87
  text "0" at 10058.63,7612.45 h90.87
  text "0" at 10095.06,7612.45 h90.87
  text "0" at 10131.49,7612.45 h90.87
  text "5" at 6770.57,7512.03 h85.82
  text "L" at 7030.7,7512.03 h85.82
  text "5" at 7072.33,7512.03 h85.82
  text "-" at 7113.97,7512.04 h85.82
  text "P" at 7139.99,7512.03 h85.82
  text "W" at 7192.03,7512.03 h85.82
  text "R" at 7270.1,7512.03 h85.82
  text "1" at 7327.35,7512.03 h85.82
  text "G" at 7769.46,7512.03 h85.82
  text "4" at 7826.71,7512.03 h85.82
  text "C" at 8081.62,7512.03 h85.82
  text "o" at 8138.86,7512.03 h85.82
  text "p" at 8180.5,7512.02 h85.82
  text "p" at 8222.13,7512.02 h85.82
  text "e" at 8263.77,7512.03 h85.82
  text "r" at 8305.4,7512.03 h85.82
  text "1" at 10417.57,7508.36 h90.87
  text "5" at 10454,7508.36 h90.87
  text "1" at 10818.17,7508.36 h90.87
  text "/" at 10854.6,7508.36 h90.87
  text "2" at 10885.83,7508.36 h90.87
  text "P" at 8081.62,7407.94 h85.82
  text "r" at 8133.66,7407.94 h85.82
  text "e" at 8159.68,7407.94 h85.82
  text "p" at 8201.32,7407.93 h85.82
  text "r" at 8242.95,7407.94 h85.82
  text "e" at 8268.97,7407.94 h85.82
  text "g" at 8310.61,7407.93 h85.82
  text "P" at 8617.48,7404.27 h90.87
  text "P" at 8659.12,7404.27 h90.87
  text "(" at 8700.75,7404.28 h90.87
  text "1" at 8726.77,7404.27 h90.87
  text "0" at 8763.2,7404.27 h90.87
  text "8" at 8799.63,7404.27 h90.87
  text "0" at 8836.07,7404.27 h90.87
  text ")" at 8872.5,7404.28 h90.87
  text "R" at 8898.52,7404.27 h90.87
  text "C" at 8940.15,7404.27 h90.87
  text "7" at 8981.79,7404.27 h90.87
  text "1" at 9018.22,7404.27 h90.87
  text "3" at 9605.97,7404.27 h90.87
  text "." at 9642.4,7404.27 h90.87
  text "9" at 9663.22,7404.27 h90.87
  text "3" at 9985.76,7404.27 h90.87
  text "." at 10022.19,7404.27 h90.87
  text "2" at 10043.01,7404.27 h90.87
  text "9" at 10079.44,7404.27 h90.87
  text "1" at 10115.87,7404.27 h90.87
  text "6" at 6770.57,7303.85 h85.82
  text "L" at 7030.7,7303.85 h85.82
  text "6" at 7072.33,7303.85 h85.82
  text "-" at 7113.97,7303.87 h85.82
  text "P" at 7139.99,7303.85 h85.82
  text "W" at 7192.03,7303.85 h85.82
  text "R" at 7270.1,7303.85 h85.82
  text "2" at 7327.35,7303.85 h85.82
  text "G" at 7769.46,7303.85 h85.82
  text "5" at 7826.71,7303.85 h85.82
  text "C" at 8081.62,7303.85 h85.82
  text "o" at 8138.86,7303.85 h85.82
  text "p" at 8180.5,7303.84 h85.82
  text "p" at 8222.13,7303.84 h85.82
  text "e" at 8263.77,7303.85 h85.82
  text "r" at 8305.4,7303.85 h85.82
  text "1" at 10417.57,7300.18 h90.87
  text "5" at 10454,7300.19 h90.87
  text "1" at 10818.17,7300.18 h90.87
  text "/" at 10854.6,7300.19 h90.87
  text "2" at 10885.83,7300.18 h90.87
  text "C" at 8081.62,7199.77 h85.82
  text "o" at 8138.86,7199.77 h85.82
  text "r" at 8180.5,7199.77 h85.82
  text "e" at 8206.52,7199.77 h85.82
  text "2" at 8617.48,7196.1 h90.87
  text "*" at 8653.91,7196.09 h90.87
  text "7" at 8690.34,7196.1 h90.87
  text "6" at 8726.77,7196.1 h90.87
  text "2" at 8763.2,7196.1 h90.87
  text "8" at 8799.63,7196.1 h90.87
  text "(" at 8851.68,7196.1 h90.87
  text "R" at 8877.7,7196.1 h90.87
  text "C" at 8919.34,7196.1 h90.87
  text "5" at 8960.97,7196.1 h90.87
  text "0" at 8997.4,7196.1 h90.87
  text ")" at 9033.83,7196.1 h90.87
  text "4" at 9605.97,7196.1 h90.87
  text "." at 9642.4,7196.1 h90.87
  text "6" at 9663.22,7196.1 h90.87
  text "1" at 9964.95,7196.1 h90.87
  text "6" at 10001.38,7196.1 h90.87
  text "." at 10037.81,7196.1 h90.87
  text "0" at 10058.63,7196.1 h90.87
  text "0" at 10095.06,7196.1 h90.87
  text "0" at 10131.49,7196.1 h90.87
  text "7" at 6770.57,7095.68 h85.82
  text "L" at 7030.7,7095.68 h85.82
  text "7" at 7072.33,7095.68 h85.82
  text "-" at 7113.97,7095.69 h85.82
  text "G" at 7139.99,7095.68 h85.82
  text "N" at 7197.24,7095.68 h85.82
  text "D" at 7249.28,7095.68 h85.82
  text "G" at 7769.46,7095.68 h85.82
  text "6" at 7826.71,7095.68 h85.82
  text "C" at 8081.62,7095.68 h85.82
  text "o" at 8138.86,7095.68 h85.82
  text "p" at 8180.5,7095.67 h85.82
  text "p" at 8222.13,7095.67 h85.82
  text "e" at 8263.77,7095.68 h85.82
  text "r" at 8305.4,7095.68 h85.82
  text "1" at 10417.57,7092.01 h90.87
  text "5" at 10454,7092.01 h90.87
  text "1" at 10818.17,7092.01 h90.87
  text "/" at 10854.6,7092.01 h90.87
  text "2" at 10885.83,7092.01 h90.87
  text "P" at 8081.62,6991.59 h85.82
  text "r" at 8133.66,6991.59 h85.82
  text "e" at 8159.68,6991.59 h85.82
  text "p" at 8201.32,6991.58 h85.82
  text "r" at 8242.95,6991.59 h85.82
  text "e" at 8268.97,6991.59 h85.82
  text "g" at 8310.61,6991.58 h85.82
  text "P" at 8617.48,6987.92 h90.87
  text "P" at 8659.12,6987.92 h90.87
  text "(" at 8700.75,6987.93 h90.87
  text "1" at 8726.77,6987.92 h90.87
  text "0" at 8763.2,6987.92 h90.87
  text "8" at 8799.63,6987.92 h90.87
  text "0" at 8836.07,6987.92 h90.87
  text ")" at 8872.5,6987.93 h90.87
  text "R" at 8898.52,6987.92 h90.87
  text "C" at 8940.15,6987.92 h90.87
  text "7" at 8981.79,6987.92 h90.87
  text "1" at 9018.22,6987.92 h90.87
  text "3" at 9605.97,6987.92 h90.87
  text "." at 9642.4,6987.92 h90.87
  text "9" at 9663.22,6987.92 h90.87
  text "3" at 9985.76,6987.92 h90.87
  text "." at 10022.19,6987.92 h90.87
  text "0" at 10043.01,6987.92 h90.87
  text "5" at 10079.44,6987.92 h90.87
  text "5" at 10115.87,6987.92 h90.87
  text "8" at 6770.57,6887.5 h85.82
  text "L" at 7030.7,6887.5 h85.82
  text "8" at 7072.33,6887.5 h85.82
  text "-" at 7113.97,6887.52 h85.82
  text "S" at 7139.99,6887.5 h85.82
  text "I" at 7192.03,6887.5 h85.82
  text "G" at 7207.65,6887.5 h85.82
  text "2" at 7264.89,6887.5 h85.82
  text "G" at 7769.46,6887.5 h85.82
  text "7" at 7826.71,6887.5 h85.82
  text "C" at 8081.62,6887.5 h85.82
  text "o" at 8138.86,6887.5 h85.82
  text "e" at 8263.77,6887.5 h85.82
  text "r" at 8305.4,6887.5 h85.82
  text "p" at 8180.5,6887.49 h85.82
  text "p" at 8222.13,6887.49 h85.82
  text "1" at 10417.57,6883.83 h90.87
  text "5" at 10454,6883.83 h90.87
  text "1" at 10818.17,6883.83 h90.87
  text "/" at 10854.6,6883.84 h90.87
  text "2" at 10885.83,6883.83 h90.87
  text "5" at 11374.85,6883.83 h90.87
  text "0" at 11411.28,6883.83 h90.87
  text "4" at 11832.67,6883.83 h90.87
  text "." at 11869.1,6883.83 h90.87
  text "0" at 11889.92,6883.83 h90.87
  text "5" at 11926.35,6883.83 h90.87
  text "9" at 12358.13,6883.83 h90.87
  text "0" at 12394.56,6883.83 h90.87
  text "3" at 12665.08,6883.83 h90.87
  text "." at 12701.51,6883.83 h90.87
  text "8" at 12722.33,6883.83 h90.87
  text "5" at 12758.76,6883.83 h90.87
  text "/" at 12810.81,6883.84 h90.87
  text "5" at 12857.65,6883.83 h90.87
  text "." at 12894.08,6883.83 h90.87
  text "1" at 12914.89,6883.83 h90.87
  text "5" at 12951.32,6883.83 h90.87
  text "1" at 13258.18,6883.83 h90.87
  text "0" at 13294.61,6883.83 h90.87
  text "0" at 13331.04,6883.83 h90.87
  text "3" at 13580.74,6883.83 h90.87
  text "." at 13617.17,6883.83 h90.87
  text "1" at 13637.98,6883.83 h90.87
  text "5" at 13674.42,6883.83 h90.87
  text "/" at 13726.46,6883.84 h90.87
  text "5" at 13773.3,6883.83 h90.87
  text "." at 13809.73,6883.83 h90.87
  text "8" at 13830.55,6883.83 h90.87
  text "5" at 13866.98,6883.83 h90.87
  text "C" at 8081.62,6783.42 h85.82
  text "o" at 8138.86,6783.42 h85.82
  text "r" at 8180.5,6783.42 h85.82
  text "e" at 8206.52,6783.42 h85.82
  text "2" at 8617.48,6779.75 h90.87
  text "*" at 8653.91,6779.74 h90.87
  text "7" at 8690.34,6779.75 h90.87
  text "6" at 8726.77,6779.75 h90.87
  text "2" at 8763.2,6779.75 h90.87
  text "8" at 8799.63,6779.75 h90.87
  text "(" at 8851.68,6779.75 h90.87
  text "R" at 8877.7,6779.75 h90.87
  text "C" at 8919.34,6779.75 h90.87
  text "5" at 8960.97,6779.75 h90.87
  text "0" at 8997.4,6779.75 h90.87
  text ")" at 9033.83,6779.75 h90.87
  text "4" at 9605.97,6779.75 h90.87
  text "." at 9642.4,6779.75 h90.87
  text "6" at 9663.22,6779.75 h90.87
  text "1" at 9964.95,6779.75 h90.87
  text "6" at 10001.38,6779.75 h90.87
  text "." at 10037.81,6779.75 h90.87
  text "0" at 10058.63,6779.75 h90.87
  text "0" at 10095.06,6779.75 h90.87
  text "0" at 10131.49,6779.75 h90.87
  text "9" at 6770.57,6679.33 h85.82
  text "L" at 7030.7,6679.33 h85.82
  text "9" at 7072.33,6679.33 h85.82
  text "-" at 7113.97,6679.34 h85.82
  text "G" at 7139.99,6679.33 h85.82
  text "N" at 7197.24,6679.33 h85.82
  text "D" at 7249.28,6679.33 h85.82
  text "G" at 7769.46,6679.33 h85.82
  text "8" at 7826.71,6679.33 h85.82
  text "C" at 8081.62,6679.33 h85.82
  text "o" at 8138.86,6679.33 h85.82
  text "p" at 8180.5,6679.32 h85.82
  text "p" at 8222.13,6679.32 h85.82
  text "e" at 8263.77,6679.33 h85.82
  text "r" at 8305.4,6679.33 h85.82
  text "1" at 10417.57,6675.66 h90.87
  text "5" at 10454,6675.66 h90.87
  text "1" at 10818.17,6675.66 h90.87
  text "/" at 10854.6,6675.66 h90.87
  text "2" at 10885.83,6675.66 h90.87
  text "P" at 8081.62,6575.24 h85.82
  text "r" at 8133.66,6575.24 h85.82
  text "e" at 8159.68,6575.24 h85.82
  text "p" at 8201.32,6575.23 h85.82
  text "r" at 8242.95,6575.24 h85.82
  text "e" at 8268.97,6575.24 h85.82
  text "g" at 8310.61,6575.23 h85.82
  text "P" at 8617.48,6571.57 h90.87
  text "P" at 8659.12,6571.57 h90.87
  text "(" at 8700.75,6571.58 h90.87
  text "1" at 8726.77,6571.57 h90.87
  text "0" at 8763.2,6571.57 h90.87
  text "8" at 8799.63,6571.57 h90.87
  text "0" at 8836.07,6571.57 h90.87
  text ")" at 8872.5,6571.58 h90.87
  text "R" at 8898.52,6571.57 h90.87
  text "C" at 8940.15,6571.57 h90.87
  text "7" at 8981.79,6571.57 h90.87
  text "1" at 9018.22,6571.57 h90.87
  text "3" at 9605.97,6571.57 h90.87
  text "." at 9642.4,6571.57 h90.87
  text "9" at 9663.22,6571.57 h90.87
  text "2" at 9985.76,6571.57 h90.87
  text "." at 10022.19,6571.57 h90.87
  text "9" at 10043.01,6571.57 h90.87
  text "7" at 10079.44,6571.57 h90.87
  text "2" at 10115.87,6571.57 h90.87
  text "1" at 6770.57,6471.15 h85.82
  text "0" at 6812.2,6471.15 h85.82
  text "L" at 7030.7,6471.15 h85.82
  text "1" at 7072.33,6471.15 h85.82
  text "0" at 7113.97,6471.15 h85.82
  text "-" at 7155.6,6471.17 h85.82
  text "B" at 7181.62,6471.15 h85.82
  text "O" at 7233.67,6471.15 h85.82
  text "T" at 7296.12,6471.15 h85.82
  text "G" at 7769.46,6471.15 h85.82
  text "B" at 7826.71,6471.15 h85.82
  text "L" at 7878.75,6471.15 h85.82
  text "C" at 8081.62,6471.15 h85.82
  text "o" at 8138.86,6471.15 h85.82
  text "p" at 8180.5,6471.14 h85.82
  text "p" at 8222.13,6471.14 h85.82
  text "e" at 8263.77,6471.15 h85.82
  text "r" at 8305.4,6471.15 h85.82
  text "3" at 10370.75,6467.48 h90.87
  text "0" at 10407.18,6467.48 h90.87
  text "-" at 10443.61,6467.48 h90.87
  text "5" at 10469.63,6467.48 h90.87
  text "0" at 10506.06,6467.48 h90.87
  text "1" at 10672.5,6467.48 h90.87
  text "/" at 10708.93,6467.49 h90.87
  text "3" at 10740.15,6467.48 h90.87
  text "+" at 10792.2,6467.48 h90.87
  text "p" at 10844.24,6467.49 h90.87
  text "l" at 10885.88,6467.48 h90.87
  text "a" at 10906.69,6467.48 h90.87
  text "t" at 10943.13,6467.48 h90.87
  text "i" at 10969.15,6467.48 h90.87
  text "n" at 10989.97,6467.48 h90.87
  text "g" at 11031.6,6467.49 h90.87
  text "5" at 11374.85,6467.48 h90.87
  text "0" at 11411.28,6467.48 h90.87
  text "4" at 11832.67,6467.48 h90.87
  text "." at 11869.1,6467.48 h90.87
  text "5" at 11889.92,6467.48 h90.87
  text "5" at 11926.35,6467.48 h90.87
  text "9" at 12358.13,6467.48 h90.87
  text "0" at 12394.56,6467.48 h90.87
  text "4" at 12665.08,6467.48 h90.87
  text "." at 12701.51,6467.48 h90.87
  text "0" at 12722.33,6467.48 h90.87
  text "5" at 12758.76,6467.48 h90.87
  text "/" at 12810.81,6467.49 h90.87
  text "4" at 12857.65,6467.48 h90.87
  text "." at 12894.08,6467.48 h90.87
  text "9" at 12914.89,6467.48 h90.87
  text "5" at 12951.32,6467.48 h90.87
  text "1" at 13258.18,6467.48 h90.87
  text "0" at 13294.61,6467.48 h90.87
  text "0" at 13331.04,6467.48 h90.87
  text "3" at 13580.74,6467.48 h90.87
  text "." at 13617.17,6467.48 h90.87
  text "3" at 13637.98,6467.48 h90.87
  text "0" at 13674.42,6467.48 h90.87
  text "/" at 13726.46,6467.49 h90.87
  text "5" at 13773.3,6467.48 h90.87
  text "." at 13809.73,6467.48 h90.87
  text "7" at 13830.55,6467.48 h90.87
  text "0" at 13866.98,6467.48 h90.87
  text "S" at 7030.7,6367.06 h85.82
  text "o" at 7082.74,6367.06 h85.82
  text "l" at 7124.38,6367.07 h85.82
  text "d" at 7139.99,6367.06 h85.82
  text "e" at 7181.62,6367.06 h85.82
  text "r" at 7223.26,6367.07 h85.82
  text "M" at 7270.1,6367.07 h85.82
  text "a" at 7327.35,6367.06 h85.82
  text "s" at 7368.98,6367.06 h85.82
  text "k" at 7410.62,6367.07 h85.82
  text "B" at 7467.86,6367.07 h85.82
  text "o" at 7519.91,6367.06 h85.82
  text "t" at 7561.54,6367.07 h85.82
  text "t" at 7582.36,6367.07 h85.82
  text "o" at 7603.18,6367.06 h85.82
  text "m" at 7644.81,6367.07 h85.82
  text "G" at 7769.46,6367.06 h85.82
  text "B" at 7826.71,6367.07 h85.82
  text "S" at 7878.75,6367.06 h85.82
  text "S" at 8081.62,6367.06 h85.82
  text "o" at 8133.66,6367.06 h85.82
  text "l" at 8175.3,6367.07 h85.82
  text "d" at 8190.91,6367.06 h85.82
  text "e" at 8232.54,6367.06 h85.82
  text "r" at 8274.18,6367.07 h85.82
  text "R" at 8321.02,6367.07 h85.82
  text "e" at 8378.27,6367.06 h85.82
  text "s" at 8419.9,6367.06 h85.82
  text "i" at 8461.54,6367.07 h85.82
  text "s" at 8477.15,6367.06 h85.82
  text "t" at 8518.78,6367.07 h85.82
  text "3" at 9605.97,6363.4 h90.87
  text "." at 9642.4,6363.4 h90.87
  text "5" at 9663.22,6363.4 h90.87
  text "O" at 7030.7,6262.98 h85.82
  text "v" at 7093.15,6262.98 h85.82
  text "e" at 7129.58,6262.98 h85.82
  text "r" at 7171.21,6262.98 h85.82
  text "l" at 7197.24,6262.98 h85.82
  text "a" at 7212.85,6262.98 h85.82
  text "y" at 7254.48,6262.96 h85.82
  text "B" at 7311.73,6262.98 h85.82
  text "o" at 7363.78,6262.98 h85.82
  text "t" at 7405.41,6262.98 h85.82
  text "t" at 7426.23,6262.98 h85.82
  text "o" at 7447.05,6262.98 h85.82
  text "m" at 7488.68,6262.98 h85.82
  text "G" at 7769.46,6262.98 h85.82
  text "B" at 7826.71,6262.98 h85.82
  text "O" at 7878.75,6262.98 h85.82
  text "S" at 8081.62,6262.98 h85.82
  text "i" at 8133.66,6262.98 h85.82
  text "l" at 8149.27,6262.98 h85.82
  text "k" at 8164.89,6262.98 h85.82
  text "s" at 8201.32,6262.98 h85.82
  text "c" at 8242.95,6262.98 h85.82
  text "r" at 8284.59,6262.98 h85.82
  text "e" at 8310.61,6262.98 h85.82
  text "e" at 8352.24,6262.98 h85.82
  text "n" at 8393.88,6262.98 h85.82
  text "NOTES: /  / 1. MATERIAL: /    IT-180A or equivalent /    Surface finish: ENIG /    Overall thickness: 90 mils +/-10% /  / 2. Fabricate to IPC-6012 (latest revision), Class II /  / 3. SOLDER RESIST: Glossy blue LPI applied over bare copper or gold/nickel plating /  / 4. SILKSCREEN: White /  / 5. LOT CODE IDENTIFICATION: /    Supplier must add identifier and lot code date to silkscreen. /    LOT CODE DATE FORMAT: YYWW (YY = 2-digit year, WW = 2-digit week) /  / 6. Drill sizes are finished size after plating /  / 7. 100% electrical bare board test required for continuity /  / 8. IMPEDANCE CONTROL: /    See Layer Stackup Table on this drawing and refer to '.Part_Number'-PCBStackup.pdf /    Short trace impedance measurements may default to TDR coupons. /  / 9. PANELIZATION: /    1 piece per array /    Tab routing required. Tab locations indicated by ::: (see Dimensions Gerber layer) /    0.25-inch rails on all sides /  / 10. POFV: All vias 10-mil diameter and smaller must be plated over filled via using non-conductive epoxy /  / 11. ROHS: Fabricate to meet EU RoHS directive. Supplier must add lead-free marking in silkscreen. /  / 12. UL certification mark required (94V-0) /  / 13. Remove all non-functional pads from internal layers" at -275.59,5962.39 h50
